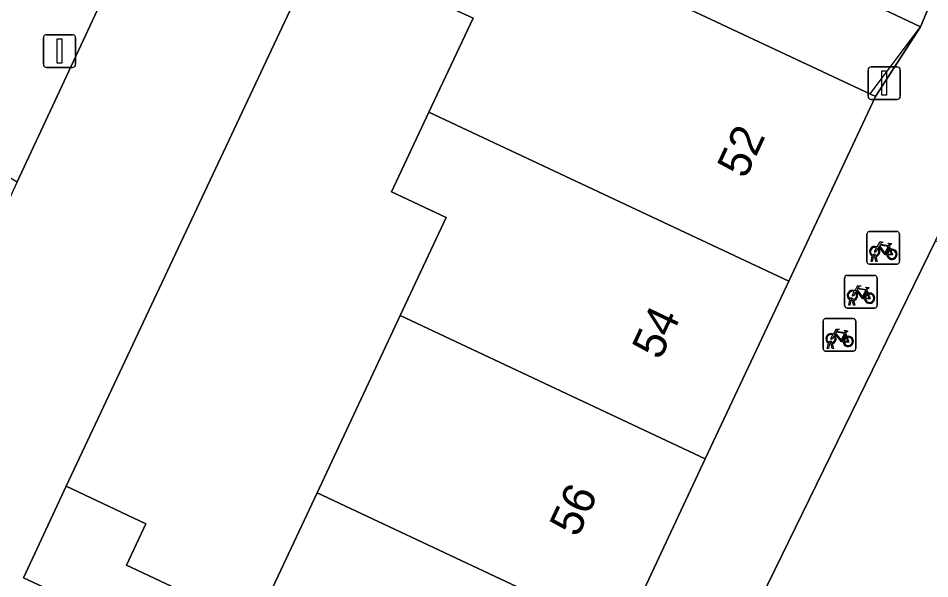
# Model space of a CAD drawing. Extents: x 160102 to 160934, y 382045 to 382923.
# Drawn here: x 160847.81 to 160875.75, y 382739.38 to 382756.55 of the extents above; entities that cross this region are included whole.
import ezdxf

# ---------------------------------------------------------------- set-up
doc = ezdxf.new("R2010")
doc.units = 0
for name, color, linetype in [('IMGEO_Erf', 7, 'Continuous'), ('IMGEO_Fietsenrek', 7, 'Continuous'), ('IMGEO_Groenvoorziening', 7, 'Continuous'), ('IMGEO_Hek', 7, 'Continuous'), ('IMGEO_Lichtmast', 7, 'Continuous'), ('IMGEO_Muur', 7, 'Continuous'), ('IMGEO_Pand', 7, 'Continuous'), ('IMGEO_Pand_nummerreeks', 7, 'Continuous'), ('IMGEO_Rijbaan_lokaal_open', 7, 'Continuous'), ('IMGEO_Voetpad_open', 7, 'Continuous')]:
    doc.layers.add(name, color=color, linetype=linetype)

msp = doc.modelspace()

# ---------------------------------------------------------------- linework, layer by layer
at = {"layer": 'IMGEO_Erf'}
msp.add_lwpolyline([(160859.256, 382751.226), (160860.401, 382753.665), (160861.753, 382756.544), (160857.045, 382758.717), (160849.284, 382742.212), (160850.209, 382741.778), (160851.728, 382741.063), (160851.132, 382739.797), (160855.065, 382737.947), (160856.973, 382742.011), (160859.522, 382747.44), (160860.93, 382750.44)], close=True, dxfattribs=at)
at = {"layer": 'IMGEO_Fietsenrek'}
for p, q in [((160873.825, 382749.089), (160873.825, 382749.93)), ((160873.825, 382749.93), (160873.825, 382749.089)), ((160873.9, 382750.014), (160874.741, 382750.014)), ((160874.741, 382750.014), (160873.9, 382750.014)), ((160874.825, 382749.939), (160874.825, 382749.098)), ((160874.825, 382749.098), (160874.825, 382749.939)), ((160874.512, 382749.563), (160874.548, 382749.468)), ((160873.952, 382749.098), (160873.991, 382749.258)), ((160874.021, 382749.246), (160873.986, 382749.098)), ((160874.063, 382749.27), (160874.062, 382749.274)), ((160874.104, 382749.098), (160874.07, 382749.24)), ((160874.094, 382749.281), (160874.095, 382749.274)), ((160874.102, 382749.244), (160874.137, 382749.098)), ((160874.75, 382749.014), (160873.909, 382749.014)), ((160873.909, 382749.014), (160874.75, 382749.014)), ((160873.986, 382749.098), (160873.952, 382749.098)), ((160874.137, 382749.098), (160874.104, 382749.098)), ((160873.216, 382748.669), (160874.057, 382748.669)), ((160874.057, 382748.669), (160873.216, 382748.669)), ((160873.141, 382747.744), (160873.141, 382748.585)), ((160873.141, 382748.585), (160873.141, 382747.744)), ((160874.141, 382748.594), (160874.141, 382747.753)), ((160874.141, 382747.753), (160874.141, 382748.594)), ((160873.828, 382748.218), (160873.864, 382748.123)), ((160873.268, 382747.753), (160873.307, 382747.913)), ((160873.337, 382747.901), (160873.302, 382747.753)), ((160873.379, 382747.925), (160873.378, 382747.929)), ((160873.42, 382747.753), (160873.386, 382747.895)), ((160873.41, 382747.936), (160873.411, 382747.929)), ((160873.418, 382747.899), (160873.453, 382747.753)), ((160874.066, 382747.669), (160873.225, 382747.669)), ((160873.225, 382747.669), (160874.066, 382747.669)), ((160873.302, 382747.753), (160873.268, 382747.753)), ((160873.453, 382747.753), (160873.42, 382747.753)), ((160872.485, 382746.422), (160872.485, 382747.263)), ((160872.485, 382747.263), (160872.485, 382746.422)), ((160872.56, 382747.347), (160873.401, 382747.347)), ((160873.401, 382747.347), (160872.56, 382747.347)), ((160873.485, 382747.272), (160873.485, 382746.431)), ((160873.485, 382746.431), (160873.485, 382747.272)), ((160873.172, 382746.896), (160873.208, 382746.801)), ((160872.612, 382746.431), (160872.651, 382746.591)), ((160872.646, 382746.431), (160872.612, 382746.431)), ((160872.681, 382746.579), (160872.646, 382746.431)), ((160872.723, 382746.603), (160872.722, 382746.607)), ((160872.764, 382746.431), (160872.73, 382746.573)), ((160872.754, 382746.614), (160872.755, 382746.607)), ((160872.762, 382746.577), (160872.797, 382746.431)), ((160872.797, 382746.431), (160872.764, 382746.431)), ((160873.41, 382746.347), (160872.569, 382746.347)), ((160872.569, 382746.347), (160873.41, 382746.347))]:
    msp.add_line(p, q, dxfattribs=at)
for points in [[(160874.159, 382749.488), (160874.107, 382749.398), (160874.067, 382749.373), (160874.068, 382749.42), (160874.123, 382749.514)], [(160874.138, 382749.54), (160874.233, 382749.704), (160874.319, 382749.69), (160874.321, 382749.681), (160874.265, 382749.67), (160874.238, 382749.625), (160874.494, 382749.584)], [(160874.434, 382749.296), (160874.384, 382749.296), (160874.193, 382749.547), (160874.174, 382749.515)], [(160874.481, 382749.559), (160874.224, 382749.6), (160874.207, 382749.571), (160874.374, 382749.351), (160874.481, 382749.559)], [(160874.529, 382749.461), (160874.499, 382749.538), (160874.39, 382749.32), (160874.433, 382749.32)], [(160874.494, 382749.584), (160874.519, 382749.633), (160874.513, 382749.637), (160874.49, 382749.641), (160874.478, 382749.648), (160874.477, 382749.651), (160874.479, 382749.656), (160874.574, 382749.641), (160874.576, 382749.631), (160874.566, 382749.618), (160874.554, 382749.612), (160874.54, 382749.618), (160874.512, 382749.563)], [(160874.463, 382749.32), (160874.583, 382749.319), (160874.539, 382749.433)], [(160874.559, 382749.44), (160874.614, 382749.295), (160874.464, 382749.295)], [(160873.454, 382748.195), (160873.549, 382748.359), (160873.635, 382748.345), (160873.637, 382748.336), (160873.581, 382748.325), (160873.554, 382748.28), (160873.81, 382748.239)], [(160873.475, 382748.143), (160873.423, 382748.053), (160873.383, 382748.028), (160873.384, 382748.075), (160873.439, 382748.169)], [(160873.75, 382747.951), (160873.7, 382747.951), (160873.509, 382748.202), (160873.49, 382748.17)], [(160873.797, 382748.214), (160873.54, 382748.255), (160873.523, 382748.226), (160873.69, 382748.006), (160873.797, 382748.214)], [(160873.845, 382748.116), (160873.815, 382748.193), (160873.706, 382747.975), (160873.749, 382747.975)], [(160873.779, 382747.975), (160873.899, 382747.974), (160873.855, 382748.088)], [(160873.875, 382748.095), (160873.93, 382747.95), (160873.78, 382747.95)], [(160873.81, 382748.239), (160873.835, 382748.288), (160873.829, 382748.292), (160873.806, 382748.296), (160873.794, 382748.303), (160873.793, 382748.306), (160873.795, 382748.311), (160873.89, 382748.296), (160873.892, 382748.286), (160873.882, 382748.273), (160873.87, 382748.267), (160873.856, 382748.273), (160873.828, 382748.218)], [(160872.798, 382746.873), (160872.893, 382747.037), (160872.979, 382747.023), (160872.981, 382747.014), (160872.925, 382747.003), (160872.898, 382746.958), (160873.154, 382746.917)], [(160873.154, 382746.917), (160873.179, 382746.966), (160873.173, 382746.97), (160873.15, 382746.974), (160873.138, 382746.981), (160873.137, 382746.984), (160873.139, 382746.989), (160873.234, 382746.974), (160873.236, 382746.964), (160873.226, 382746.951), (160873.214, 382746.945), (160873.2, 382746.951), (160873.172, 382746.896)], [(160872.819, 382746.821), (160872.767, 382746.731), (160872.727, 382746.706), (160872.728, 382746.753), (160872.783, 382746.847)], [(160873.094, 382746.629), (160873.044, 382746.629), (160872.853, 382746.88), (160872.834, 382746.848)], [(160873.141, 382746.892), (160872.884, 382746.933), (160872.867, 382746.904), (160873.034, 382746.684), (160873.141, 382746.892)], [(160873.189, 382746.794), (160873.159, 382746.871), (160873.05, 382746.653), (160873.093, 382746.653)], [(160873.123, 382746.653), (160873.243, 382746.652), (160873.199, 382746.766)], [(160873.219, 382746.773), (160873.274, 382746.628), (160873.124, 382746.628)]]:
    msp.add_lwpolyline(points, dxfattribs=at)
for centre, radius, start, end in [((160873.903, 382749.936), 0.0779, 92.4484, 184.2845), ((160873.903, 382749.936), 0.0779, 92.4484, 184.2845), ((160874.747, 382749.936), 0.0779, 2.4484, 94.2845), ((160874.747, 382749.936), 0.0779, 2.4484, 94.2845), ((160874.065, 382749.399), 0.159, 62.6766, 242.1369), ((160874.065, 382749.399), 0.129, 63.3192, 238.903), ((160874.065, 382749.399), 0.129, 283.6043, 43.4302), ((160874.065, 382749.399), 0.159, 283.5766, 46.6042), ((160874.592, 382749.315), 0.159, 187.0065, 105.7708), ((160874.045, 382749.27), 0.0499, 12.8025, 158.6934), ((160874.065, 382749.399), 0.159, 253.9967, 271.7867), ((160874.045, 382749.27), 0.0174, 12.8025, 163.4502), ((160874.065, 382749.399), 0.129, 253.415, 269.0204), ((160874.592, 382749.315), 0.159, 113.3408, 178.3217), ((160874.592, 382749.315), 0.129, 113.923, 177.9556), ((160874.592, 382749.315), 0.129, 188.6715, 104.5883), ((160873.903, 382749.092), 0.0779, 182.4484, 274.2845), ((160873.903, 382749.092), 0.0779, 182.4484, 274.2845), ((160874.747, 382749.092), 0.0779, 272.4484, 4.2845), ((160874.747, 382749.092), 0.0779, 272.4484, 4.2845), ((160873.219, 382748.591), 0.0779, 92.4484, 184.2845), ((160873.219, 382748.591), 0.0779, 92.4484, 184.2845), ((160874.063, 382748.591), 0.0779, 2.4484, 94.2845), ((160874.063, 382748.591), 0.0779, 2.4484, 94.2845), ((160873.381, 382748.054), 0.159, 62.6766, 242.1369), ((160873.381, 382748.054), 0.129, 63.3192, 238.903), ((160873.381, 382748.054), 0.129, 283.6043, 43.4302), ((160873.381, 382748.054), 0.159, 283.5766, 46.6042), ((160873.908, 382747.97), 0.159, 113.3408, 178.3217), ((160873.908, 382747.97), 0.159, 187.0065, 105.7708), ((160873.908, 382747.97), 0.129, 113.923, 177.9556), ((160873.908, 382747.97), 0.129, 188.6715, 104.5883), ((160873.361, 382747.925), 0.0499, 12.8025, 158.6934), ((160873.381, 382748.054), 0.159, 253.9967, 271.7867), ((160873.361, 382747.925), 0.0174, 12.8025, 163.4502), ((160873.381, 382748.054), 0.129, 253.415, 269.0204), ((160873.219, 382747.747), 0.0779, 182.4484, 274.2845), ((160873.219, 382747.747), 0.0779, 182.4484, 274.2845), ((160874.063, 382747.747), 0.0779, 272.4484, 4.2845), ((160874.063, 382747.747), 0.0779, 272.4484, 4.2845), ((160872.563, 382747.269), 0.0779, 92.4484, 184.2845), ((160872.563, 382747.269), 0.0779, 92.4484, 184.2845), ((160873.407, 382747.269), 0.0779, 2.4484, 94.2845), ((160873.407, 382747.269), 0.0779, 2.4484, 94.2845), ((160872.725, 382746.732), 0.159, 62.6766, 242.1369), ((160872.725, 382746.732), 0.129, 63.3192, 238.903), ((160872.725, 382746.732), 0.129, 283.6043, 43.4302), ((160872.725, 382746.732), 0.159, 283.5766, 46.6042), ((160873.252, 382746.648), 0.159, 113.3408, 178.3217), ((160873.252, 382746.648), 0.159, 187.0065, 105.7708), ((160873.252, 382746.648), 0.129, 113.923, 177.9556), ((160873.252, 382746.648), 0.129, 188.6715, 104.5883), ((160872.563, 382746.425), 0.0779, 182.4484, 274.2845), ((160872.563, 382746.425), 0.0779, 182.4484, 274.2845), ((160872.705, 382746.603), 0.0499, 12.8025, 158.6934), ((160872.725, 382746.732), 0.159, 253.9967, 271.7867), ((160872.705, 382746.603), 0.0174, 12.8025, 163.4502), ((160872.725, 382746.732), 0.129, 253.415, 269.0204), ((160873.407, 382746.425), 0.0779, 272.4484, 4.2845), ((160873.407, 382746.425), 0.0779, 272.4484, 4.2845)]:
    msp.add_arc(centre, radius, start, end, dxfattribs=at)
at = {"layer": 'IMGEO_Groenvoorziening'}
msp.add_lwpolyline([(160832.254, 382760.853), (160847.78, 382751.534), (160851.387, 382759.264)], dxfattribs=at)
at = {"layer": 'IMGEO_Hek'}
msp.add_lwpolyline([(160873.922, 382754.228), (160875.47, 382756.281)], dxfattribs=at)
at = {"layer": 'IMGEO_Lichtmast'}
for p, q in [((160848.583, 382755.142), (160848.583, 382755.942)), ((160848.583, 382755.942), (160848.583, 382755.142)), ((160848.683, 382756.042), (160849.473, 382756.042)), ((160849.473, 382756.042), (160848.683, 382756.042)), ((160849.573, 382755.942), (160849.573, 382755.142)), ((160849.573, 382755.142), (160849.573, 382755.942)), ((160849.473, 382755.042), (160848.683, 382755.042)), ((160848.683, 382755.042), (160849.473, 382755.042)), ((160873.86, 382754.16), (160873.86, 382754.96)), ((160873.86, 382754.96), (160873.86, 382754.16)), ((160873.96, 382755.06), (160874.75, 382755.06)), ((160874.75, 382755.06), (160873.96, 382755.06)), ((160874.85, 382754.96), (160874.85, 382754.16)), ((160874.85, 382754.16), (160874.85, 382754.96)), ((160874.75, 382754.06), (160873.96, 382754.06)), ((160873.96, 382754.06), (160874.75, 382754.06))]:
    msp.add_line(p, q, dxfattribs=at)
for points in [[(160849.003, 382755.917), (160849.153, 382755.917), (160849.153, 382755.167), (160849.003, 382755.167), (160849.003, 382755.917)], [(160874.28, 382754.935), (160874.43, 382754.935), (160874.43, 382754.185), (160874.28, 382754.185), (160874.28, 382754.935)]]:
    msp.add_lwpolyline(points, dxfattribs=at)
for centre, start, end in [((160848.683, 382755.942), 90, 180), ((160848.683, 382755.942), 90, 180), ((160849.473, 382755.942), 0, 90), ((160849.473, 382755.942), 360, 90), ((160848.683, 382755.142), 180, 270), ((160848.683, 382755.142), 180, 270), ((160849.473, 382755.142), 270, 0), ((160849.473, 382755.142), 270, 0), ((160873.96, 382754.96), 90, 180), ((160873.96, 382754.96), 90, 180), ((160874.75, 382754.96), 0, 90), ((160874.75, 382754.96), 360, 90), ((160873.96, 382754.16), 180, 270), ((160873.96, 382754.16), 180, 270), ((160874.75, 382754.16), 270, 0), ((160874.75, 382754.16), 270, 0)]:
    msp.add_arc(centre, 0.1, start, end, dxfattribs=at)
at = {"layer": 'IMGEO_Muur'}
msp.add_lwpolyline([(160857.045, 382758.717), (160849.284, 382742.212)], dxfattribs=at)
at = {"layer": 'IMGEO_Pand'}
for points in [[(160870.655, 382768.224), (160864.409, 382770.935), (160863.489, 382768.997), (160863.68, 382768.906), (160864.28, 382766.698), (160862.611, 382764.85), (160868.142, 382759.756), (160875.47, 382756.281), (160877.92, 382762.125), (160878.904, 382764.441)], [(160871.428, 382748.493), (160874.085, 382754.152), (160858.349, 382761.529), (160857.045, 382758.717), (160861.753, 382756.544), (160860.401, 382753.665), (160862.075, 382752.878)], [(160871.428, 382748.493), (160862.075, 382752.878), (160860.401, 382753.665), (160859.256, 382751.226), (160860.93, 382750.44), (160859.522, 382747.44), (160868.872, 382743.049)], [(160866.322, 382737.618), (160868.872, 382743.049), (160859.522, 382747.44), (160856.973, 382742.011)], [(160856.973, 382742.011), (160855.065, 382737.947), (160851.132, 382739.797), (160851.728, 382741.063), (160850.209, 382741.778), (160849.284, 382742.212), (160847.977, 382739.405), (160848.871, 382738.983), (160859.907, 382733.781), (160863.684, 382732), (160866.322, 382737.618)]]:
    msp.add_lwpolyline(points, close=True, dxfattribs=at)
at = {"layer": 'IMGEO_Rijbaan_lokaal_open'}
for points in [[(160848.871, 382738.983), (160847.977, 382739.405), (160849.284, 382742.212), (160857.045, 382758.717), (160858.349, 382761.529), (160864.175, 382773.992), (160870.234, 382786.936), (160865.965, 382790.473), (160865.463, 382789.419), (160862.922, 382784.019), (160860.656, 382779.204), (160859.334, 382776.335), (160855.156, 382767.252), (160854.243, 382765.384), (160851.387, 382759.264), (160847.78, 382751.534), (160846.897, 382749.655), (160841.095, 382737.186), (160840.341, 382735.558), (160832.435, 382718.448), (160829.713, 382712.474)], [(160862.964, 382715.042), (160872.597, 382725.314), (160876.319, 382733.988), (160881.824, 382746.815), (160875.933, 382749.726), (160869.922, 382737.434)]]:
    msp.add_lwpolyline(points, dxfattribs=at)
at = {"layer": 'IMGEO_Voetpad_open'}
for points in [[(160869.922, 382737.434), (160875.933, 382749.726), (160876.197, 382750.267), (160883.479, 382765.119), (160897.018, 382796.438), (160909.834, 382827.177), (160911.478, 382831.312)], [(160877.92, 382762.125), (160875.47, 382756.281), (160874.085, 382754.152), (160871.428, 382748.493), (160868.872, 382743.049), (160866.322, 382737.618), (160863.684, 382732), (160860.158, 382725.372), (160856.738, 382726.921), (160855.848, 382725.002), (160859.131, 382723.493), (160852.146, 382710.453), (160847.846, 382712.429), (160845.942, 382708.331)]]:
    msp.add_lwpolyline(points, dxfattribs=at)
msp.add_lwpolyline([(160868.368, 382779.113), (160871.573, 382786.148), (160870.621, 382786.622), (160870.234, 382786.936), (160864.175, 382773.992), (160858.349, 382761.529), (160874.085, 382754.152), (160875.47, 382756.281), (160868.142, 382759.756), (160862.611, 382764.85), (160861.728, 382765.67), (160862.495, 382766.9), (160863.489, 382768.997), (160864.409, 382770.935)], close=True, dxfattribs=at)

# ---------------------------------------------------------------- texts
at = {"layer": 'IMGEO_Pand_nummerreeks'}
for s, rotation, p in [('52', 65.0031, (160870.102, 382751.597)), ('54', 64.7407, (160867.49, 382746.047)), ('56', 64.7407, (160864.958, 382740.614))]:
    msp.add_text(s, height=1, rotation=rotation, dxfattribs=at).set_placement(p)

doc.saveas('drawing.dxf')
